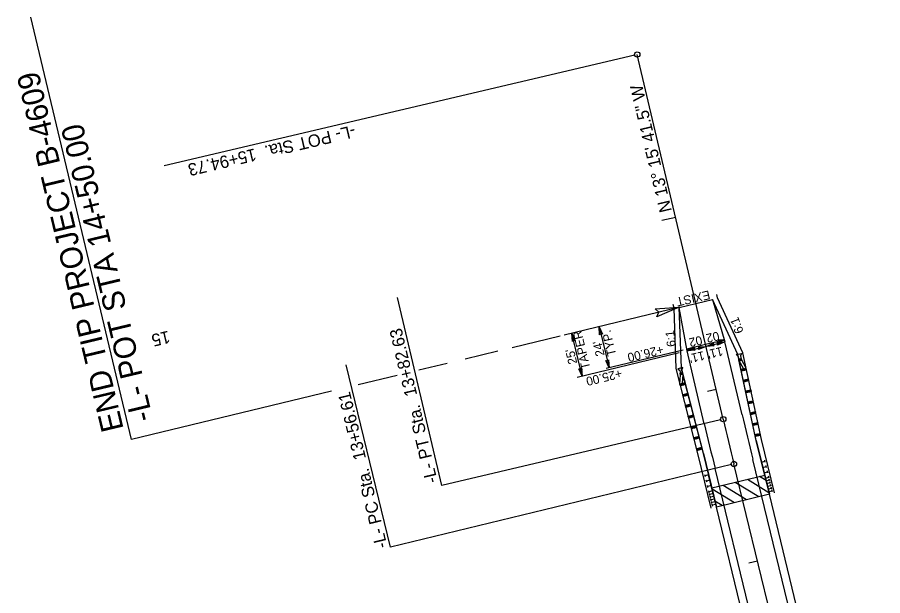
# Model space of a CAD drawing. Extents: x 1735795 to 1737428, y 699740 to 701024.
# Drawn here: x 1735795.3 to 1736285, y 700466.8 to 700794.2 of the extents above; entities that cross this region are included whole.
import ezdxf

# ---------------------------------------------------------------- set-up
doc = ezdxf.new("R2010")
doc.units = 0
for name, color, linetype in [('Prop Approach Slab', 7, 'Continuous'), ('Prop Approach Slab Hatching', 7, 'Continuous'), ('Prop Conc Shoulder Berm Gutter', 7, 'Continuous'), ('Prop Dimension', 7, 'Continuous'), ('Prop Dimension Text', 7, 'Continuous'), ('Prop DSN Text', 7, 'Continuous'), ('Prop EOT', 7, 'Continuous'), ('Prop Guardrail', 7, 'Continuous'), ('Prop Guardrail Anchor Unit CELL', 7, 'Continuous'), ('Prop Horizontal Alignment', 7, 'Continuous'), ('Prop Horizontal Alignment Direction Label', 7, 'Continuous'), ('Prop Horizontal Alignment Station Label', 7, 'Continuous'), ('Prop Horizontal Alignment Tick Label', 7, 'Continuous'), ('Prop Horizontal Alignment Tick Large', 7, 'Continuous'), ('Prop Horizontal Alignment Tick Small', 7, 'Continuous'), ('Prop Leader Line Heavy', 7, 'Continuous'), ('Prop Paved Shoulder', 7, 'Continuous'), ('Prop Roadway Bridge', 7, 'Continuous'), ('Prop Structure Anchor Unit CELL', 7, 'Continuous'), ('Prop Superelevation  Arrow CELL', 7, 'Continuous'), ('Prop Terminator CELL', 7, 'Continuous'), ('Scratch_Level_1', 7, 'Continuous'), ('Scratch_Level_2', 7, 'Continuous')]:
    doc.layers.add(name, color=color, linetype=linetype)

msp = doc.modelspace()

# ---------------------------------------------------------------- linework, layer by layer
at = {"layer": 'Prop Approach Slab'}
for p, q in [((1736218.25, 700534.89), (1736188.29, 700527.61)), ((1736220.84, 700524.2), (1736218.25, 700534.89)), ((1736190.88, 700516.92), (1736188.29, 700527.61)), ((1736220.84, 700524.2), (1736190.88, 700516.92))]:
    msp.add_line(p, q, dxfattribs=at)
at = {"layer": 'Prop Approach Slab Hatching'}
for p, q in [((1736220.64, 700525.04), (1736208.42, 700532.5)), ((1736218.97, 700531.92), (1736215.28, 700534.17)), ((1736201.08, 700519.41), (1736188.39, 700527.16)), ((1736207.96, 700521.07), (1736194.7, 700529.17)), ((1736214.83, 700522.73), (1736201.56, 700530.84)), ((1736194.21, 700517.75), (1736190.07, 700520.28))]:
    msp.add_line(p, q, dxfattribs=at)
at = {"layer": 'Prop Conc Shoulder Berm Gutter'}
for p, q in [((1736220.84, 700524.22), (1736216.41, 700542.44)), ((1736190.88, 700516.94), (1736186.45, 700535.16))]:
    msp.add_line(p, q, dxfattribs=at)
at = {"layer": 'Prop Dimension'}
for p, q in [((1736114.86, 700590.98), (1736109.09, 700615.31)), ((1736174.33, 700605.4), (1736195.74, 700610.45)), ((1736172.12, 700605.84), (1736128.5, 700595.31)), ((1736169.79, 700604.24), (1736112.01, 700590.3))]:
    msp.add_line(p, q, dxfattribs=at)
at = {"layer": 'Prop EOT'}
for p, q in [((1736169.89, 700629.99), (1736188.68, 700634.52)), ((1736174.33, 700605.4), (1736169.89, 700629.99)), ((1736188.68, 700634.52), (1736195.74, 700610.45)), ((1736205.46, 700569.21), (1736195.74, 700610.45)), ((1736184.04, 700564.16), (1736174.33, 700605.4)), ((1736256.89, 700357.09), (1736211.5, 700543.97)), ((1736261.3, 700245.69), (1736190.12, 700538.78))]:
    msp.add_line(p, q, dxfattribs=at)
for radius in [3808.72, 3830.72]:
    msp.add_arc((1739912.61, 701442.92), radius, 193.26153, 193.65186, dxfattribs=at)
at = {"layer": 'Prop Guardrail'}
for p, q in [((1736216.41, 700542.44), (1736213.46, 700554.59)), ((1736183.5, 700547.31), (1736186.45, 700535.16))]:
    msp.add_line(p, q, dxfattribs=at)
at = {"layer": 'Prop Guardrail Anchor Unit CELL'}
for p, q in [((1736202.15, 700603.29), (1736205.01, 700603.96)), ((1736203.25, 700602.34), (1736202.15, 700603.29)), ((1736203.72, 700600.35), (1736203.25, 700602.34)), ((1736203.55, 700600.79), (1736205.01, 700601.1)), ((1736203.55, 700600.79), (1736205.22, 700600.12)), ((1736213.46, 700554.59), (1736203.65, 700600.3)), ((1736204.31, 700600.48), (1736203.72, 700600.35)), ((1736205.01, 700601.1), (1736203.76, 700599.81)), ((1736204.91, 700600.62), (1736204.31, 700600.48)), ((1736205.01, 700603.96), (1736204.44, 700602.61)), ((1736204.44, 700602.61), (1736204.91, 700600.62)), ((1736205.22, 700600.12), (1736205.01, 700601.1)), ((1736205.22, 700600.12), (1736205.12, 700600.61)), ((1736171.88, 700595.94), (1736169.02, 700595.26)), ((1736171.31, 700594.6), (1736171.88, 700595.94)), ((1736203.76, 700599.81), (1736205.22, 700600.12)), ((1736206.28, 700595.34), (1736203.76, 700599.81)), ((1736204.78, 700595.02), (1736207.78, 700595.66)), ((1736207.78, 700595.66), (1736205.22, 700600.12)), ((1736207.78, 700595.66), (1736206.49, 700594.36)), ((1736207.99, 700594.68), (1736207.78, 700595.66)), ((1736169.02, 700595.26), (1736170.13, 700594.31)), ((1736170.13, 700594.31), (1736170.6, 700592.32)), ((1736170.24, 700586.6), (1736170.54, 700591.73)), ((1736171.74, 700593.08), (1736170.29, 700592.7)), ((1736170.54, 700591.73), (1736170.29, 700592.7)), ((1736170.29, 700592.7), (1736171.99, 700592.11)), ((1736170.54, 700591.73), (1736170.42, 700592.22)), ((1736171.74, 700593.08), (1736170.54, 700591.73)), ((1736171.99, 700592.11), (1736170.54, 700591.73)), ((1736170.6, 700592.32), (1736171.19, 700592.46)), ((1736171.19, 700592.46), (1736171.79, 700592.6)), ((1736171.79, 700592.6), (1736171.31, 700594.6)), ((1736171.73, 700586.98), (1736171.99, 700592.11)), ((1736183.5, 700547.31), (1736171.87, 700592.59)), ((1736206.49, 700594.36), (1736204.78, 700595.02)), ((1736204.99, 700594.04), (1736206.28, 700595.34)), ((1736204.99, 700594.04), (1736207.99, 700594.68)), ((1736206.49, 700594.36), (1736206.28, 700595.34)), ((1736206.28, 700595.34), (1736207.99, 700594.68)), ((1736173.21, 700587.36), (1736170.24, 700586.6)), ((1736170.49, 700585.63), (1736170.24, 700586.6)), ((1736170.24, 700586.6), (1736171.98, 700586.01)), ((1736171.73, 700586.98), (1736170.49, 700585.63)), ((1736173.46, 700586.39), (1736170.49, 700585.63)), ((1736171.98, 700586.01), (1736171.73, 700586.98)), ((1736173.46, 700586.39), (1736171.73, 700586.98)), ((1736171.98, 700586.01), (1736173.21, 700587.36)), ((1736206.11, 700588.86), (1736209.04, 700589.49)), ((1736207.78, 700588.19), (1736206.11, 700588.86)), ((1736206.32, 700587.88), (1736207.57, 700589.17)), ((1736206.32, 700587.88), (1736209.25, 700588.51)), ((1736207.78, 700588.19), (1736207.57, 700589.17)), ((1736207.57, 700589.17), (1736209.25, 700588.51)), ((1736209.04, 700589.49), (1736207.78, 700588.19)), ((1736209.25, 700588.51), (1736209.04, 700589.49)), ((1736174.78, 700581.26), (1736171.87, 700580.51)), ((1736173.33, 700580.88), (1736172.12, 700579.54)), ((1736173.58, 700579.91), (1736173.33, 700580.88)), ((1736175.03, 700580.29), (1736173.33, 700580.88)), ((1736173.58, 700579.91), (1736174.78, 700581.26)), ((1736207.43, 700582.7), (1736210.5, 700583.35)), ((1736209.17, 700582.05), (1736207.43, 700582.7)), ((1736207.64, 700581.72), (1736208.96, 700583.02)), ((1736207.64, 700581.72), (1736210.71, 700582.38)), ((1736209.17, 700582.05), (1736208.96, 700583.02)), ((1736208.96, 700583.02), (1736210.71, 700582.38)), ((1736210.5, 700583.35), (1736209.17, 700582.05)), ((1736210.71, 700582.38), (1736210.5, 700583.35)), ((1736172.12, 700579.54), (1736171.87, 700580.51)), ((1736171.87, 700580.51), (1736173.58, 700579.91)), ((1736175.03, 700580.29), (1736172.12, 700579.54)), ((1736208.75, 700576.53), (1736211.72, 700577.17)), ((1736208.96, 700575.56), (1736208.75, 700576.53)), ((1736210.45, 700575.88), (1736208.75, 700576.53)), ((1736208.96, 700575.56), (1736210.24, 700576.85)), ((1736208.96, 700575.56), (1736211.93, 700576.19)), ((1736210.45, 700575.88), (1736210.24, 700576.85)), ((1736210.24, 700576.85), (1736211.93, 700576.19)), ((1736211.72, 700577.17), (1736210.45, 700575.88)), ((1736211.93, 700576.19), (1736211.72, 700577.17)), ((1736176.35, 700575.15), (1736173.31, 700574.37)), ((1736173.56, 700573.4), (1736173.31, 700574.37)), ((1736173.31, 700574.37), (1736175.08, 700573.79)), ((1736174.83, 700574.76), (1736173.56, 700573.4)), ((1736176.6, 700574.19), (1736173.56, 700573.4)), ((1736175.08, 700573.79), (1736174.83, 700574.76)), ((1736176.6, 700574.19), (1736174.83, 700574.76)), ((1736175.08, 700573.79), (1736176.35, 700575.15)), ((1736210.08, 700570.37), (1736213.05, 700571.01)), ((1736213.05, 700571.01), (1736211.78, 700569.72)), ((1736213.26, 700570.03), (1736213.05, 700571.01)), ((1736177.92, 700569.05), (1736174.98, 700568.3)), ((1736175.22, 700567.33), (1736174.98, 700568.3)), ((1736174.98, 700568.3), (1736176.69, 700567.7)), ((1736176.45, 700568.67), (1736175.22, 700567.33)), ((1736178.16, 700568.08), (1736175.22, 700567.33)), ((1736176.69, 700567.7), (1736176.45, 700568.67)), ((1736178.16, 700568.08), (1736176.45, 700568.67)), ((1736176.69, 700567.7), (1736177.92, 700569.05)), ((1736178.16, 700568.08), (1736177.92, 700569.05)), ((1736211.78, 700569.72), (1736210.08, 700570.37)), ((1736210.29, 700569.4), (1736211.57, 700570.69)), ((1736210.29, 700569.4), (1736213.26, 700570.03)), ((1736211.78, 700569.72), (1736211.57, 700570.69)), ((1736211.57, 700570.69), (1736213.26, 700570.03)), ((1736179.48, 700562.95), (1736176.53, 700562.19)), ((1736176.78, 700561.22), (1736176.53, 700562.19)), ((1736176.53, 700562.19), (1736178.26, 700561.6)), ((1736178.01, 700562.57), (1736176.78, 700561.22)), ((1736179.73, 700561.98), (1736176.78, 700561.22)), ((1736178.26, 700561.6), (1736178.01, 700562.57)), ((1736179.73, 700561.98), (1736178.01, 700562.57)), ((1736178.26, 700561.6), (1736179.48, 700562.95)), ((1736211.4, 700564.21), (1736214.38, 700564.85)), ((1736213.1, 700563.56), (1736211.4, 700564.21)), ((1736211.61, 700563.23), (1736212.89, 700564.53)), ((1736211.61, 700563.23), (1736214.59, 700563.88)), ((1736213.1, 700563.56), (1736212.89, 700564.53)), ((1736212.89, 700564.53), (1736214.59, 700563.88)), ((1736214.38, 700564.85), (1736213.1, 700563.56)), ((1736214.59, 700563.88), (1736214.38, 700564.85)), ((1736181.05, 700556.84), (1736178.09, 700556.09)), ((1736179.57, 700556.47), (1736178.34, 700555.12)), ((1736179.82, 700555.5), (1736179.57, 700556.47)), ((1736181.3, 700555.88), (1736179.57, 700556.47)), ((1736179.82, 700555.5), (1736181.05, 700556.84)), ((1736212.72, 700558.05), (1736215.65, 700558.68)), ((1736212.72, 700558.05), (1736214.19, 700558.37)), ((1736212.93, 700557.07), (1736212.72, 700558.05)), ((1736214.4, 700557.39), (1736212.72, 700558.05)), ((1736214.19, 700558.37), (1736212.93, 700557.07)), ((1736212.93, 700557.07), (1736215.86, 700557.7)), ((1736214.4, 700557.39), (1736214.19, 700558.37)), ((1736214.19, 700558.37), (1736215.86, 700557.7)), ((1736215.65, 700558.68), (1736214.4, 700557.39)), ((1736215.86, 700557.7), (1736215.65, 700558.68)), ((1736178.34, 700555.12), (1736178.09, 700556.09)), ((1736178.09, 700556.09), (1736179.82, 700555.5)), ((1736181.3, 700555.88), (1736178.34, 700555.12)), ((1736182.62, 700550.74), (1736179.71, 700550)), ((1736179.96, 700549.03), (1736179.71, 700550)), ((1736179.71, 700550), (1736181.42, 700549.4)), ((1736181.17, 700550.37), (1736179.96, 700549.03)), ((1736182.87, 700549.77), (1736179.96, 700549.03)), ((1736182.62, 700550.74), (1736181.17, 700550.37)), ((1736181.42, 700549.4), (1736181.17, 700550.37)), ((1736181.17, 700550.37), (1736182.87, 700549.77)), ((1736181.42, 700549.4), (1736182.62, 700550.74)), ((1736182.87, 700549.77), (1736182.62, 700550.74))]:
    msp.add_line(p, q, dxfattribs=at)
at = {"layer": 'Prop Horizontal Alignment'}
for p, q in [((1736194.75, 700566.69), (1736146.1, 700773.13)), ((1736284.97, 700194.84), (1736200.81, 700541.38))]:
    msp.add_line(p, q, dxfattribs=at)
msp.add_arc((1739912.61, 701442.92), 3819.72, 193.26153, 193.65186, dxfattribs=at)
at = {"layer": 'Prop Horizontal Alignment Station Label'}
for p, q in [((1736144.64, 700772.78), (1735878.43, 700710.04)), ((1736035.42, 700529.13), (1736010.33, 700635.58)), ((1736006.38, 700494.16), (1735981.29, 700597.45)), ((1736193.29, 700566.34), (1736035.42, 700529.13)), ((1736199.35, 700541.02), (1736006.38, 700494.16))]:
    msp.add_line(p, q, dxfattribs=at)
for centre in [(1736146.1, 700773.13), (1736194.75, 700566.69), (1736200.81, 700541.38)]:
    msp.add_circle(centre, 1.5, dxfattribs=at)
at = {"layer": 'Prop Horizontal Alignment Tick Large'}
msp.add_line((1736167.83, 700680.92), (1736160.04, 700679.09), dxfattribs=at)
at = {"layer": 'Prop Horizontal Alignment Tick Small'}
for p, q in [((1736190.77, 700583.59), (1736185.9, 700582.44)), ((1736214.17, 700486.37), (1736209.31, 700485.19))]:
    msp.add_line(p, q, dxfattribs=at)
at = {"layer": 'Prop Leader Line Heavy'}
for p, q in [((1735859.93, 700555.15), (1735802.89, 700794.2)), ((1736170.2, 700630.06), (1736104.81, 700614.27)), ((1736102.52, 700613.72), (1736075.24, 700607.14)), ((1736067.27, 700605.21), (1736048.8, 700600.75)), ((1736038.44, 700598.25), (1736022.48, 700594.4)), ((1736010.23, 700591.44), (1735988.23, 700586.13)), ((1735973.11, 700582.48), (1735859.93, 700555.15))]:
    msp.add_line(p, q, dxfattribs=at)
at = {"layer": 'Prop Paved Shoulder'}
for p, q in [((1736171.04, 700595.85), (1736169.89, 700629.99)), ((1736202.98, 700603.38), (1736188.68, 700634.52)), ((1736213.45, 700554.59), (1736202.98, 700603.38)), ((1736183.51, 700547.31), (1736171.04, 700595.85)), ((1736213.45, 700554.59), (1736220.83, 700524.22)), ((1736183.51, 700547.31), (1736190.89, 700516.95))]:
    msp.add_line(p, q, dxfattribs=at)
at = {"layer": 'Prop Roadway Bridge'}
for p, q in [((1736241.47, 700439.29), (1736220.84, 700524.2)), ((1736211.5, 700432.01), (1736190.88, 700516.92))]:
    msp.add_line(p, q, dxfattribs=at)
at = {"layer": 'Prop Structure Anchor Unit CELL'}
for p, q in [((1736216.41, 700542.44), (1736218.36, 700542.91)), ((1736220.84, 700524.22), (1736216.41, 700542.44)), ((1736218.49, 700542.36), (1736218.22, 700543.47)), ((1736217.15, 700539.4), (1736219.1, 700539.88)), ((1736217.89, 700536.37), (1736219.83, 700536.84)), ((1736219.23, 700539.32), (1736218.96, 700540.43)), ((1736219.97, 700536.28), (1736219.7, 700537.4)), ((1736184.64, 700534.13), (1736184.37, 700535.25)), ((1736186.45, 700535.16), (1736184.51, 700534.69)), ((1736185.38, 700531.1), (1736185.11, 700532.21)), ((1736187.19, 700532.13), (1736185.25, 700531.65)), ((1736190.88, 700516.94), (1736186.45, 700535.16)), ((1736218.63, 700533.33), (1736220.57, 700533.8)), ((1736219, 700531.81), (1736220.94, 700532.28)), ((1736220.71, 700533.25), (1736220.44, 700534.36)), ((1736221.07, 700531.73), (1736220.8, 700532.84)), ((1736186.12, 700528.06), (1736185.85, 700529.17)), ((1736187.93, 700529.09), (1736185.98, 700528.62)), ((1736219.36, 700530.29), (1736221.31, 700530.77)), ((1736219.73, 700528.78), (1736221.68, 700529.25)), ((1736220.1, 700527.26), (1736222.05, 700527.73)), ((1736221.44, 700530.21), (1736221.17, 700531.32)), ((1736221.81, 700528.69), (1736221.54, 700529.8)), ((1736222.18, 700527.17), (1736221.91, 700528.29)), ((1736186.86, 700525.02), (1736186.59, 700526.14)), ((1736188.66, 700526.05), (1736186.72, 700525.58)), ((1736187.22, 700523.51), (1736186.95, 700524.62)), ((1736189.03, 700524.54), (1736187.09, 700524.06)), ((1736187.59, 700521.99), (1736187.32, 700523.1)), ((1736189.4, 700523.02), (1736187.46, 700522.54)), ((1736220.47, 700525.74), (1736222.41, 700526.21)), ((1736222.55, 700525.65), (1736222.28, 700526.77)), ((1736187.96, 700520.47), (1736187.69, 700521.58)), ((1736189.77, 700521.5), (1736187.83, 700521.03)), ((1736188.33, 700518.95), (1736188.06, 700520.06)), ((1736190.14, 700519.98), (1736188.2, 700519.51)), ((1736188.7, 700517.43), (1736188.43, 700518.55)), ((1736190.51, 700518.46), (1736188.56, 700517.99))]:
    msp.add_line(p, q, dxfattribs=at)
at = {"layer": 'Prop Superelevation  Arrow CELL'}
for p, q in [((1736124.52, 700619.03), (1736130.13, 700595.7)), ((1736195.43, 700611.4), (1736184.8, 700608.9)), ((1736184.8, 700608.9), (1736174.16, 700606.39))]:
    msp.add_line(p, q, dxfattribs=at)
for points in [[(1736195.43, 700611.4), (1736191.84, 700611.39), (1736192.56, 700610.73)], [(1736174.16, 700606.39), (1736177.75, 700606.4), (1736177.04, 700607.06)]]:
    msp.add_lwpolyline(points, close=True, dxfattribs=at)
at = {"layer": 'Prop Terminator CELL'}
for points in [[(1736156.21, 700629.19), (1736169.88, 700630.04), (1736157.22, 700624.58), (1736158.35, 700627.31)], [(1736109.38, 700610.75), (1736109.09, 700615.31), (1736110.91, 700611.09), (1736110, 700611.47)], [(1736124.82, 700614.48), (1736124.52, 700619.03), (1736126.36, 700614.82), (1736125.44, 700615.19)], [(1736191.18, 700610.17), (1736195.74, 700610.45), (1736191.52, 700608.63), (1736191.89, 700609.54)], [(1736178.88, 700605.68), (1736174.33, 700605.4), (1736178.55, 700607.22), (1736178.17, 700606.31)], [(1736180.47, 700607.65), (1736185.03, 700607.92), (1736180.81, 700606.11), (1736181.19, 700607.02)], [(1736189.59, 700608.2), (1736185.03, 700607.92), (1736189.25, 700609.74), (1736188.88, 700608.83)], [(1736114.58, 700595.54), (1736114.86, 700590.98), (1736113.04, 700595.2), (1736113.95, 700594.83)], [(1736129.83, 700600.25), (1736130.13, 700595.7), (1736128.29, 700599.91), (1736129.2, 700599.54)]]:
    msp.add_lwpolyline(points, close=True, dxfattribs=at)
at = {"layer": 'Scratch_Level_1'}
for points in [[(1736220.84, 700524.22), (1736213.46, 700554.59), (1736202.99, 700603.38)], [(1736190.88, 700516.94), (1736183.5, 700547.31), (1736171.03, 700595.84)]]:
    msp.add_lwpolyline(points, dxfattribs=at)
at = {"layer": 'Scratch_Level_2'}
for p, q in [((1736205.86, 700604.29), (1736191.55, 700635.45)), ((1736168.06, 700595.37), (1736166.9, 700629.62))]:
    msp.add_line(p, q, dxfattribs=at)
for points in [[(1736191.55, 700635.45), (1736191.12, 700637.29)], [(1736166.9, 700629.62), (1736166.45, 700631.54)], [(1736223.75, 700524.93), (1736216.39, 700555.26), (1736205.86, 700604.29)], [(1736187.96, 700516.24), (1736180.59, 700546.58), (1736168.06, 700595.37)]]:
    msp.add_lwpolyline(points, dxfattribs=at)

# ---------------------------------------------------------------- texts
at = {"layer": 'Prop Dimension Text'}
for s, rotation, p in [('6:1', 110.6124, (1736206.39, 700616.25)), ('TAPER', 103.3409, (1736119.58, 700595.54)), ('6:1', 96.3976, (1736167.91, 700607.95)), ("25'", 103.3409, (1736112.16, 700598.43)), ("11'", 193.2615, (1736193.9, 700607.72)), ("11'", 193.2615, (1736183.55, 700605.3)), ('+25.00', 193.505, (1736136.8, 700595.14))]:
    msp.add_text(s, height=5, rotation=rotation, dxfattribs=at).set_placement(p)
at = {"layer": 'Prop DSN Text'}
for s, p in [('END TIP PROJECT B-4609', (1735855.53, 700561.19)), ('-L- POT STA 14+50.00', (1735872.18, 700566.74))]:
    msp.add_text(s, height=12.6, rotation=103.4195, dxfattribs=at).set_placement(p)
at = {"layer": 'Prop Horizontal Alignment Direction Label'}
msp.add_text('N 13%%d 15\' 41.5" W', height=7, rotation=103.2615, dxfattribs=at).set_placement((1736165.72, 700684.64))
at = {"layer": 'Prop Horizontal Alignment Station Label'}
for s, rotation, p in [('-L- POT Sta.  15+94.73', 193.2615, (1735985.79, 700733.29)), ('-L- PT Sta.  13+82.63', 103.2615, (1736033.21, 700531.35)), ('-L- PC Sta.  13+56.61', 103.6519, (1736004.85, 700494.49))]:
    msp.add_text(s, height=7, rotation=rotation, dxfattribs=at).set_placement(p)
at = {"layer": 'Prop Horizontal Alignment Tick Label'}
msp.add_text('15', height=7, rotation=193.2615, dxfattribs=at).set_placement((1735880.81, 700616.87))
at = {"layer": 'Prop Superelevation  Arrow CELL'}
for s, rotation, p in [('EXIST', 192.8139, (1736186.66, 700639.66)), ('TYP.', 103.3409, (1736134.25, 700603.09)), ('02', 193.0974, (1736191.89, 700616.41)), ("24'", 103.3409, (1736127.67, 700602.97)), ('02', 193.0974, (1736182.19, 700613.98)), ('+26.00', 193.3409, (1736160.26, 700608.63))]:
    msp.add_text(s, height=5, rotation=rotation, dxfattribs=at).set_placement(p)

doc.saveas('drawing.dxf')
